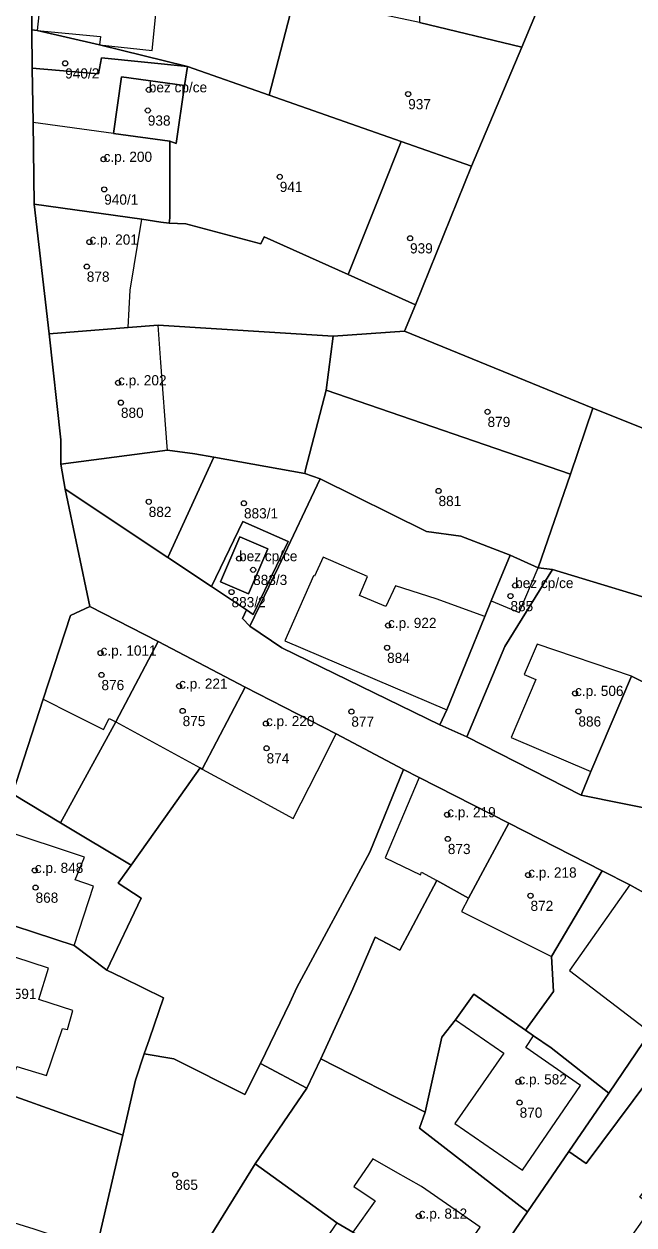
# Model space of a CAD drawing. Extents: x -878211 to -870363, y -1058464 to -1052522.
# Drawn here: x -874817.9 to -874758, y -1056517.4 to -1056399.5 of the extents above; entities that cross this region are included whole.
import ezdxf

# ---------------------------------------------------------------- set-up
doc = ezdxf.new("R2010")
doc.units = 0
for name, color, linetype in [('Definiční body', 7, 'Continuous'), ('Polygon budovy', 7, 'Continuous'), ('Polygon parcely', 7, 'Continuous')]:
    doc.layers.add(name, color=color, linetype=linetype)

msp = doc.modelspace()

# ---------------------------------------------------------------- linework, layer by layer
at = {"layer": 'Definiční body'}
for centre in [(-874813.87, -1056403.36994), (-874805.66, -1056405.96994), (-874780.2, -1056406.38994), (-874805.76, -1056407.99994), (-874810.1, -1056412.78994), (-874792.81, -1056414.50994), (-874810.04, -1056415.74994), (-874811.49, -1056420.91994), (-874780.02, -1056420.53994), (-874811.75, -1056423.31994), (-874808.68, -1056434.72994), (-874808.4, -1056436.67994), (-874772.41, -1056437.57994), (-874777.22, -1056445.33994), (-874805.67, -1056446.40994), (-874796.32, -1056446.54994), (-874796.8, -1056451.98994), (-874795.42, -1056453.08994), (-874797.54, -1056455.26994), (-874769.7, -1056454.62994), (-874770.16, -1056455.65994), (-874782.18, -1056458.54994), (-874810.4, -1056461.25994), (-874782.27, -1056460.73994), (-874810.31, -1056463.40994), (-874802.69, -1056464.50994), (-874763.82, -1056465.21994), (-874802.34, -1056466.93994), (-874785.78, -1056466.99994), (-874763.49, -1056466.97994), (-874794.16, -1056468.17994), (-874794.1, -1056470.59994), (-874776.37, -1056477.12994), (-874776.31, -1056479.49994), (-874816.85, -1056482.58994), (-874768.42, -1056483.04994), (-874816.78, -1056484.27994), (-874768.19, -1056485.07994), (-874769.38, -1056503.34994), (-874769.26, -1056505.37994), (-874803.07, -1056512.45994), (-874779.17, -1056516.52994)]:
    msp.add_circle(centre, 0.25, dxfattribs=at)
at = {"layer": 'Polygon budovy'}
for points in [[(-874816.61, -1056400.15), (-874810.42, -1056400.73), (-874810.51, -1056401.57), (-874805.33, -1056402.1), (-874804.98, -1056398.56), (-874803.89, -1056397.57), (-874803.81, -1056396.01), (-874804.62, -1056394.88), (-874804.5, -1056393.93), (-874804.39, -1056391.6), (-874811.67, -1056391.05), (-874815.66, -1056390.75), (-874816.23, -1056396.42)], [(-874809.13, -1056410.25), (-874803.6, -1056411), (-874802.98, -1056411.24), (-874802.15, -1056405.55), (-874808.34, -1056404.68)], [(-874817.01, -1056409.18), (-874816.93, -1056417.19), (-874806.35, -1056418.68), (-874804.47, -1056418.95), (-874803.65, -1056419.06), (-874803.61, -1056418.55), (-874803.6, -1056411), (-874809.13, -1056410.25)], [(-874816.93, -1056417.19), (-874815.43, -1056429.91), (-874807.68, -1056429.29), (-874807.5, -1056425.63), (-874806.35, -1056418.68)], [(-874807.68, -1056429.29), (-874815.43, -1056429.91), (-874814.29, -1056440.32), (-874814.3, -1056442.72), (-874803.83, -1056441.33), (-874803.86, -1056440.97), (-874804.47, -1056432.74), (-874804.75, -1056429.06)], [(-874796.73, -1056449.85), (-874798.64, -1056454.26), (-874795.87, -1056455.46), (-874793.97, -1056451.04)], [(-874767.44, -1056452.9), (-874770.2, -1056451.65), (-874772.05, -1056456.13), (-874769.29, -1056457.28)], [(-874789.5, -1056453.67), (-874792.3, -1056460.07), (-874776.41, -1056466.83), (-874772.69, -1056457.67), (-874777.46, -1056455.94), (-874781.46, -1056454.66), (-874782.39, -1056456.7), (-874784.97, -1056455.6), (-874784.18, -1056453.75), (-874788.56, -1056451.86), (-874789.39, -1056453.71)], [(-874813.36, -1056457.56), (-874816.03, -1056465.77), (-874813.18, -1056467.21), (-874810.11, -1056468.76), (-874809.57, -1056467.69), (-874808.9, -1056468.02), (-874804.76, -1056460.13), (-874811.44, -1056456.7)], [(-874804.76, -1056460.13), (-874808.9, -1056468.02), (-874800.61, -1056472.54), (-874800.43, -1056472.64), (-874796.2, -1056464.61)], [(-874770.09, -1056469.53), (-874762.27, -1056472.9), (-874758.27, -1056463.52), (-874767.53, -1056460.37), (-874768.8, -1056463.35), (-874767.67, -1056463.86)], [(-874800.43, -1056472.64), (-874795.52, -1056475.3), (-874791.48, -1056477.49), (-874789.14, -1056472.89), (-874787.26, -1056469.19), (-874796.2, -1056464.61)], [(-874779.11, -1056473.48), (-874782.46, -1056481.37), (-874778.98, -1056483.04), (-874778.88, -1056482.76), (-874777.39, -1056483.58), (-874774.27, -1056485.32), (-874770.31, -1056477.96)], [(-874822.8, -1056486.77), (-874812.99, -1056489.97), (-874811.08, -1056484.13), (-874812.88, -1056483.52), (-874811.97, -1056481.3), (-874820.16, -1056478.57)], [(-874774.97, -1056486.63), (-874766.12, -1056491.04), (-874761.17, -1056482.65), (-874770.31, -1056477.96), (-874774.27, -1056485.32)], [(-874764.37, -1056492.43), (-874756.45, -1056498.46), (-874750.71, -1056489.97), (-874751.15, -1056488.09), (-874758.44, -1056484)], [(-874818.62, -1056501.84), (-874815.72, -1056502.73), (-874814.12, -1056498.1), (-874813.63, -1056498.21), (-874813.12, -1056496.33), (-874816.47, -1056495.25), (-874815.51, -1056492.2), (-874823.66, -1056489.55), (-874827.73, -1056501.96), (-874820.2, -1056504.39), (-874819.53, -1056504.54)], [(-874770.82, -1056500.52), (-874775.61, -1056507.44), (-874768.97, -1056512.01), (-874763.27, -1056503.69), (-874768.66, -1056499.96), (-874767.89, -1056498.83), (-874768.7, -1056498.27), (-874773.75, -1056494.75), (-874775.56, -1056497.25)], [(-874783.45, -1056515.03), (-874785.64, -1056518.1), (-874777.44, -1056523.83), (-874773.12, -1056517.6), (-874778.9, -1056513.62), (-874781.43, -1056512.18), (-874783.68, -1056510.91), (-874785.54, -1056513.62)], [(-874790.73, -1056525.64), (-874782.57, -1056531.25), (-874777.44, -1056523.83), (-874785.64, -1056518.1), (-874787.19, -1056517.19), (-874790.37, -1056521.79), (-874788.88, -1056522.94)]]:
    msp.add_lwpolyline(points, close=True, dxfattribs=at)
at = {"layer": 'Polygon parcely'}
for points in [[(-874771.88, -1056347.58), (-874771.57, -1056349.15), (-874776.47, -1056350.13), (-874775.99, -1056352.58), (-874783.34, -1056354.04), (-874785.98, -1056354.25), (-874785.16, -1056358.37), (-874779.06, -1056381.92), (-874779.1, -1056399.35), (-874769.04, -1056401.77), (-874759.61, -1056379.22), (-874767.09, -1056346.97)], [(-874676.37, -1056404.7), (-874677.01, -1056392.06), (-874685.65, -1056392.4), (-874695.66, -1056392.71), (-874699.02, -1056385.96), (-874705.69, -1056372.77), (-874709.26, -1056366.25), (-874719.04, -1056368.48), (-874720.98, -1056368.98), (-874735.34, -1056372.63), (-874743.87, -1056374.83), (-874752.26, -1056377.07), (-874759.61, -1056379.22), (-874769.04, -1056401.77), (-874773.98, -1056413.47), (-874779.49, -1056427.06), (-874780.55, -1056429.67), (-874762.07, -1056437.23), (-874747.48, -1056443.08), (-874718.21, -1056454.5), (-874706.91, -1056430.53), (-874696.83, -1056406.55), (-874687.37, -1056405.45), (-874685.09, -1056405.18)], [(-874816.61, -1056400.15), (-874810.51, -1056401.57), (-874801.88, -1056403.67), (-874793.86, -1056406.49), (-874791.32, -1056396.73), (-874798.8, -1056395.13), (-874804.5, -1056393.93), (-874804.39, -1056391.6), (-874811.67, -1056391.05), (-874815.66, -1056390.75), (-874817.14, -1056390.64), (-874817.16, -1056400.09)], [(-874780.89, -1056411.04), (-874773.98, -1056413.47), (-874769.04, -1056401.77), (-874779.1, -1056399.35), (-874791.32, -1056396.73), (-874793.86, -1056406.49)], [(-874817.16, -1056400.09), (-874817.1, -1056403.84), (-874810.61, -1056404.41), (-874810.3, -1056402.82), (-874801.88, -1056403.67), (-874810.51, -1056401.57), (-874816.61, -1056400.15)], [(-874801.88, -1056403.67), (-874810.3, -1056402.82), (-874810.61, -1056404.41), (-874817.1, -1056403.84), (-874817.01, -1056409.18), (-874816.93, -1056417.19), (-874806.35, -1056418.68), (-874804.47, -1056418.95), (-874803.65, -1056419.06), (-874803.61, -1056418.55), (-874803.6, -1056411), (-874809.13, -1056410.25), (-874808.34, -1056404.68), (-874802.15, -1056405.55)], [(-874803.6, -1056411), (-874803.61, -1056418.55), (-874803.65, -1056419.06), (-874802.04, -1056419.14), (-874794.66, -1056421.1), (-874794.33, -1056420.39), (-874786.08, -1056424.1), (-874782.89, -1056416.08), (-874780.89, -1056411.04), (-874793.86, -1056406.49), (-874801.88, -1056403.67), (-874802.15, -1056405.55), (-874802.98, -1056411.24)], [(-874809.13, -1056410.25), (-874803.6, -1056411), (-874802.98, -1056411.24), (-874802.15, -1056405.55), (-874808.34, -1056404.68)], [(-874782.89, -1056416.08), (-874786.08, -1056424.1), (-874779.49, -1056427.06), (-874773.98, -1056413.47), (-874780.89, -1056411.04)], [(-874804.47, -1056418.95), (-874806.35, -1056418.68), (-874816.93, -1056417.19), (-874815.43, -1056429.91), (-874807.68, -1056429.29), (-874804.75, -1056429.06), (-874787.56, -1056430.15), (-874780.55, -1056429.67), (-874779.49, -1056427.06), (-874786.08, -1056424.1), (-874794.33, -1056420.39), (-874794.66, -1056421.1), (-874802.04, -1056419.14), (-874803.65, -1056419.06)], [(-874804.75, -1056429.06), (-874807.68, -1056429.29), (-874815.43, -1056429.91), (-874814.29, -1056440.32), (-874814.3, -1056442.72), (-874803.83, -1056441.33), (-874801.14, -1056441.71), (-874799.27, -1056442.04), (-874790.36, -1056443.63), (-874790.28, -1056443.24), (-874788.26, -1056435.44), (-874787.56, -1056430.15)], [(-874788.26, -1056435.44), (-874764.26, -1056443.7), (-874762.07, -1056437.23), (-874780.55, -1056429.67), (-874787.56, -1056430.15)], [(-874770.2, -1056451.65), (-874767.44, -1056452.9), (-874764.26, -1056443.7), (-874788.26, -1056435.44), (-874790.28, -1056443.24), (-874790.36, -1056443.63), (-874788.85, -1056444.14), (-874778.41, -1056449.33), (-874775.03, -1056449.77)], [(-874747.48, -1056443.08), (-874762.07, -1056437.23), (-874764.26, -1056443.7), (-874767.44, -1056452.9), (-874766.05, -1056453.04), (-874753.3, -1056456.92)], [(-874799.27, -1056442.04), (-874801.14, -1056441.71), (-874803.83, -1056441.33), (-874814.3, -1056442.72), (-874813.86, -1056445.18), (-874803.79, -1056451.88)], [(-874792.94, -1056452.79), (-874788.85, -1056444.14), (-874790.36, -1056443.63), (-874799.27, -1056442.04), (-874803.79, -1056451.88), (-874799.5, -1056454.73), (-874796.42, -1056448.36), (-874791.98, -1056450.3), (-874795.41, -1056457.46), (-874796.08, -1056457.01), (-874796.48, -1056457.88), (-874795.75, -1056458.63)], [(-874772.05, -1056456.13), (-874770.2, -1056451.65), (-874775.03, -1056449.77), (-874778.41, -1056449.33), (-874788.85, -1056444.14), (-874792.94, -1056452.79), (-874795.75, -1056458.63), (-874792.6, -1056460.75), (-874777.11, -1056468.31), (-874776.41, -1056466.83), (-874772.69, -1056457.67)], [(-874746.43, -1056481.89), (-874754.95, -1056476.89), (-874763.22, -1056475.22), (-874774.43, -1056469.49), (-874777.11, -1056468.31), (-874792.6, -1056460.75), (-874795.75, -1056458.63), (-874796.48, -1056457.88), (-874796.08, -1056457.01), (-874799.5, -1056454.73), (-874803.79, -1056451.88), (-874813.86, -1056445.18), (-874811.44, -1056456.7), (-874804.76, -1056460.13), (-874796.2, -1056464.61), (-874787.26, -1056469.19), (-874780.67, -1056472.7), (-874779.11, -1056473.48), (-874770.31, -1056477.96), (-874761.17, -1056482.65), (-874758.44, -1056484), (-874751.15, -1056488.09)], [(-874796.08, -1056457.01), (-874795.41, -1056457.46), (-874791.98, -1056450.3), (-874796.42, -1056448.36), (-874799.5, -1056454.73)], [(-874796.73, -1056449.85), (-874793.97, -1056451.04), (-874795.87, -1056455.46), (-874798.64, -1056454.26)], [(-874796.73, -1056449.85), (-874798.64, -1056454.26), (-874795.87, -1056455.46), (-874793.97, -1056451.04)], [(-874767.44, -1056452.9), (-874770.2, -1056451.65), (-874772.05, -1056456.13), (-874772.69, -1056457.67), (-874776.41, -1056466.83), (-874777.11, -1056468.31), (-874774.43, -1056469.49), (-874770.7, -1056460.63), (-874766.05, -1056453.04)], [(-874758.27, -1056463.52), (-874757.22, -1056464.04), (-874756.19, -1056464.33), (-874753.3, -1056456.92), (-874766.05, -1056453.04), (-874770.7, -1056460.63), (-874774.43, -1056469.49), (-874763.22, -1056475.22), (-874762.27, -1056472.9)], [(-874804.76, -1056460.13), (-874811.44, -1056456.7), (-874813.36, -1056457.56), (-874816.03, -1056465.77), (-874819.04, -1056475.08), (-874814.33, -1056477.92), (-874808.9, -1056468.02)], [(-874745.05, -1056477.8), (-874742.21, -1056468.41), (-874744.75, -1056467.68), (-874743.73, -1056464.03), (-874742.87, -1056460.95), (-874753.3, -1056456.92), (-874756.19, -1056464.33), (-874757.22, -1056464.04), (-874758.27, -1056463.52), (-874762.27, -1056472.9), (-874763.22, -1056475.22), (-874754.95, -1056476.89), (-874746.43, -1056481.89)], [(-874808.9, -1056468.02), (-874814.33, -1056477.92), (-874807.41, -1056482.09), (-874803.47, -1056476.55), (-874800.61, -1056472.54), (-874800.43, -1056472.64), (-874796.2, -1056464.61), (-874804.76, -1056460.13)], [(-874803.47, -1056476.55), (-874807.41, -1056482.09), (-874808.66, -1056483.84), (-874806.4, -1056485.31), (-874809.77, -1056492.4), (-874808.2, -1056493.13), (-874804.23, -1056495.11), (-874805.59, -1056499.13), (-874806.13, -1056500.61), (-874803.21, -1056501.09), (-874796.25, -1056504.59), (-874794.71, -1056501.53), (-874791.81, -1056495.59), (-874791.14, -1056494.08), (-874783.98, -1056480.8), (-874780.67, -1056472.7), (-874787.26, -1056469.19), (-874796.2, -1056464.61), (-874800.43, -1056472.64), (-874800.61, -1056472.54)], [(-874791.81, -1056495.59), (-874794.71, -1056501.53), (-874790.16, -1056503.96), (-874788.78, -1056501.09), (-874785.63, -1056494.21), (-874783.43, -1056489.14), (-874781.01, -1056490.42), (-874780, -1056488.51), (-874777.39, -1056483.58), (-874774.27, -1056485.32), (-874770.31, -1056477.96), (-874779.11, -1056473.48), (-874780.67, -1056472.7), (-874783.98, -1056480.8), (-874791.14, -1056494.08)], [(-874814.33, -1056477.92), (-874819.04, -1056475.08), (-874820.16, -1056478.57), (-874822.8, -1056486.77), (-874812.99, -1056489.97), (-874809.77, -1056492.4), (-874806.4, -1056485.31), (-874808.66, -1056483.84), (-874807.41, -1056482.09)], [(-874785.63, -1056494.21), (-874788.78, -1056501.09), (-874778.52, -1056506.33), (-874776.91, -1056498.96), (-874775.56, -1056497.25), (-874773.75, -1056494.75), (-874768.7, -1056498.27), (-874765.94, -1056494.47), (-874766.12, -1056491.04), (-874761.17, -1056482.65), (-874770.31, -1056477.96), (-874774.27, -1056485.32), (-874777.39, -1056483.58), (-874780, -1056488.51), (-874781.01, -1056490.42), (-874783.43, -1056489.14)], [(-874756.45, -1056498.46), (-874750.71, -1056489.97), (-874751.15, -1056488.09), (-874758.44, -1056484), (-874761.17, -1056482.65), (-874766.12, -1056491.04), (-874765.94, -1056494.47), (-874768.7, -1056498.27), (-874767.89, -1056498.83), (-874766.17, -1056500.02), (-874760.51, -1056504.47)], [(-874804.23, -1056495.11), (-874808.2, -1056493.13), (-874809.77, -1056492.4), (-874812.99, -1056489.97), (-874822.8, -1056486.77), (-874823.66, -1056489.55), (-874827.73, -1056501.96), (-874820.2, -1056504.39), (-874819.53, -1056504.54), (-874808.2, -1056508.58), (-874806.96, -1056503.19), (-874806.13, -1056500.61), (-874805.59, -1056499.13)], [(-874760.51, -1056504.47), (-874764.42, -1056510.19), (-874762.73, -1056511.37), (-874755.04, -1056501.07), (-874749.51, -1056494.67), (-874747.99, -1056493.3), (-874749.7, -1056488.95), (-874750.71, -1056489.97), (-874756.45, -1056498.46)], [(-874760.51, -1056504.47), (-874766.17, -1056500.02), (-874767.89, -1056498.83), (-874768.7, -1056498.27), (-874773.75, -1056494.75), (-874775.56, -1056497.25), (-874776.91, -1056498.96), (-874778.52, -1056506.33), (-874779.09, -1056507.89), (-874768.48, -1056516.12), (-874764.42, -1056510.19)], [(-874806.13, -1056500.61), (-874806.96, -1056503.19), (-874808.2, -1056508.58), (-874809.78, -1056515.36), (-874810.84, -1056519.83), (-874814.29, -1056532.05), (-874809.74, -1056533.41), (-874806.38, -1056528.2), (-874800.08, -1056519.21), (-874795.21, -1056511.41), (-874790.16, -1056503.96), (-874794.71, -1056501.53), (-874796.25, -1056504.59), (-874803.21, -1056501.09)], [(-874768.48, -1056516.12), (-874779.09, -1056507.89), (-874778.52, -1056506.33), (-874788.78, -1056501.09), (-874790.16, -1056503.96), (-874795.21, -1056511.41), (-874787.19, -1056517.19), (-874785.64, -1056518.1), (-874777.44, -1056523.83), (-874775.04, -1056525.67)], [(-874820.2, -1056504.39), (-874827.73, -1056501.96), (-874831.43, -1056513.29), (-874823.81, -1056515.64), (-874816.96, -1056517.78), (-874810.84, -1056519.83), (-874809.78, -1056515.36), (-874808.2, -1056508.58), (-874819.53, -1056504.54)], [(-874775.04, -1056525.67), (-874777.44, -1056523.83), (-874785.64, -1056518.1), (-874787.19, -1056517.19), (-874795.21, -1056511.41), (-874800.08, -1056519.21), (-874798.1, -1056520.57), (-874790.73, -1056525.64), (-874782.57, -1056531.25), (-874780.04, -1056532.99)]]:
    msp.add_lwpolyline(points, close=True, dxfattribs=at)
for points in [[(-874835.36, -1056525.38), (-874831.43, -1056513.29), (-874827.73, -1056501.96), (-874823.66, -1056489.55), (-874822.8, -1056486.77), (-874820.16, -1056478.57), (-874819.04, -1056475.08), (-874816.03, -1056465.77), (-874813.36, -1056457.56), (-874811.44, -1056456.7), (-874813.86, -1056445.18), (-874814.3, -1056442.72), (-874814.29, -1056440.32), (-874815.43, -1056429.91), (-874816.93, -1056417.19), (-874817.01, -1056409.18), (-874817.1, -1056403.84), (-874817.16, -1056400.09), (-874817.14, -1056390.64)], [(-874763.27, -1056525.64), (-874756.17, -1056515.56), (-874757.46, -1056514.66), (-874749.04, -1056503.26), (-874745.11, -1056498.8), (-874744.03, -1056497.83), (-874741.22, -1056495.96), (-874738.12, -1056494.14), (-874738.7, -1056484.54), (-874738.95, -1056484.44), (-874738.71, -1056484.33), (-874746.43, -1056481.89), (-874751.15, -1056488.09), (-874750.71, -1056489.97), (-874749.7, -1056488.95), (-874747.99, -1056493.3), (-874749.51, -1056494.67), (-874755.04, -1056501.07), (-874762.73, -1056511.37), (-874764.42, -1056510.19), (-874768.48, -1056516.12), (-874775.04, -1056525.67)]]:
    msp.add_lwpolyline(points, dxfattribs=at)

# ---------------------------------------------------------------- texts
at = {"layer": 'Definiční body'}
for s, p in [('940/2', (-874813.87, -1056404.859)), ('bez cp/ce', (-874805.66, -1056406.22)), ('937', (-874780.2, -1056407.879)), ('938', (-874805.76, -1056409.489)), ('c.p. 200', (-874810.1, -1056413.04)), ('941', (-874792.81, -1056415.999)), ('940/1', (-874810.04, -1056417.239)), ('c.p. 201', (-874811.49, -1056421.169)), ('939', (-874780.02, -1056422.029)), ('878', (-874811.75, -1056424.809)), ('c.p. 202', (-874808.68, -1056434.98)), ('880', (-874808.4, -1056438.169)), ('879', (-874772.41, -1056439.069)), ('882', (-874805.67, -1056447.899)), ('883/1', (-874796.32, -1056448.039)), ('881', (-874777.22, -1056446.829)), ('bez cp/ce', (-874796.8, -1056452.24)), ('883/3', (-874795.42, -1056454.579)), ('bez cp/ce', (-874769.7, -1056454.879)), ('883/2', (-874797.54, -1056456.759)), ('885', (-874770.16, -1056457.149)), ('c.p. 922', (-874782.18, -1056458.8)), ('c.p. 1011', (-874810.4, -1056461.51)), ('884', (-874782.27, -1056462.229)), ('876', (-874810.31, -1056464.899)), ('c.p. 221', (-874802.69, -1056464.76)), ('c.p. 506', (-874763.82, -1056465.47)), ('875', (-874802.34, -1056468.429)), ('c.p. 220', (-874794.16, -1056468.429)), ('877', (-874785.78, -1056468.489)), ('886', (-874763.49, -1056468.469)), ('874', (-874794.1, -1056472.089)), ('c.p. 219', (-874776.37, -1056477.379)), ('873', (-874776.31, -1056480.989)), ('c.p. 848', (-874816.85, -1056482.84)), ('c.p. 218', (-874768.42, -1056483.3)), ('868', (-874816.78, -1056485.769)), ('872', (-874768.19, -1056486.569)), ('c.p. 591', (-874821.45, -1056495.21)), ('c.p. 582', (-874769.38, -1056503.6)), ('870', (-874769.26, -1056506.869)), ('865', (-874803.07, -1056513.949)), ('c.p. 812', (-874779.17, -1056516.78))]:
    msp.add_text(s, height=0.999996, dxfattribs=at).set_placement(p)

doc.saveas('drawing.dxf')
